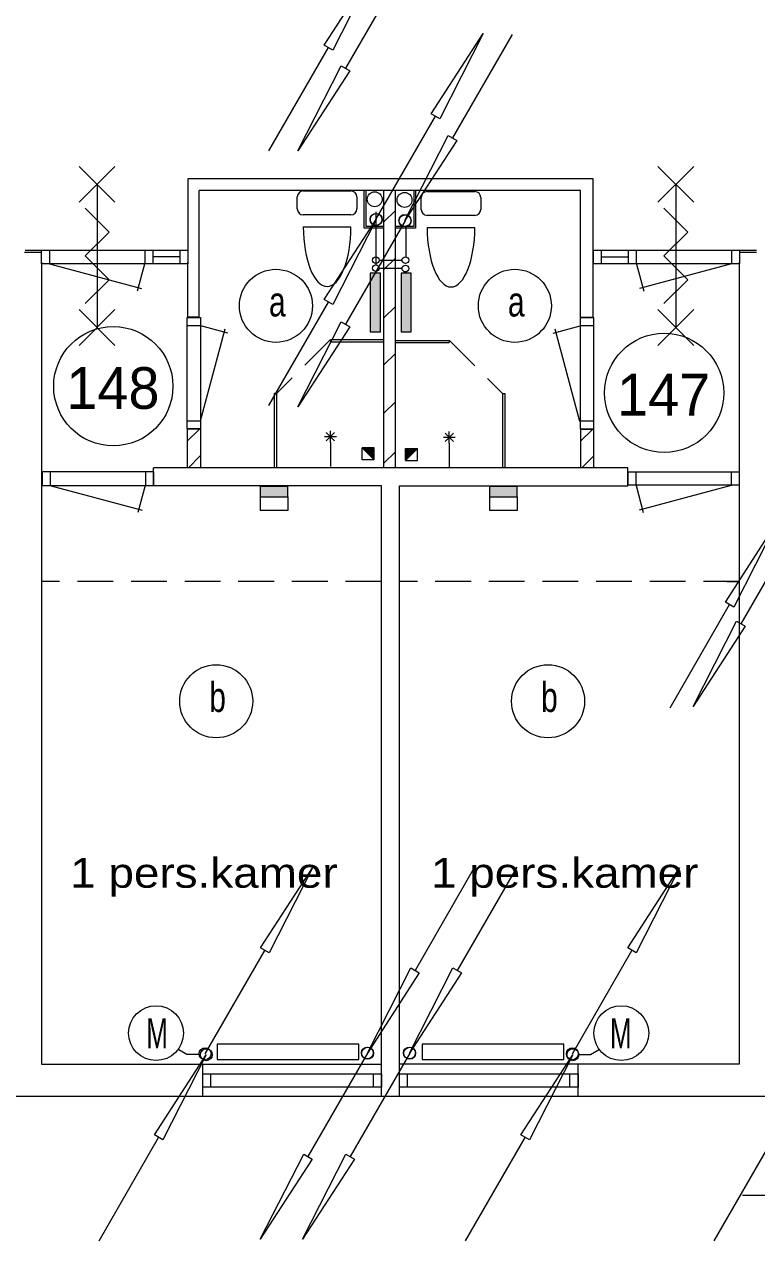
# Model space of a CAD drawing. Extents: x 295824 to 414724, y 24924 to 109024.
# Drawn here: x 319942 to 326087, y 61088 to 71286 of the extents above; entities that cross this region are included whole.
import ezdxf
from ezdxf.enums import TextEntityAlignment as Align

# ---------------------------------------------------------------- set-up
doc = ezdxf.new("R2010")
doc.units = 0
doc.header["$LTSCALE"] = 100
doc.linetypes.add('LONG_DASHED', pattern=[7.5, 6, -1.5])
doc.linetypes.add('MEDIUM_DASHED', pattern=[4.5, 3, -1.5])
doc.layers.add('16', color=7, linetype='Continuous', lineweight=13)
doc.layers.add('61', color=7, linetype='Continuous', lineweight=13)

msp = doc.modelspace()

# ---------------------------------------------------------------- hatches: boundary and pattern name
at = {"layer": '16'}
for points in [[(322843.9, 68706.6), (322929.4, 68706.6), (322929.4, 69198.8), (322843.9, 69198.8)], [(323103.1, 68706.6), (323188.5, 68706.6), (323188.5, 69198.8), (323103.1, 69198.8)], [(322152.7, 67410.5), (321921.2, 67410.5), (321921.2, 67324), (322152.7, 67324)], [(324077.6, 67410.5), (323846.1, 67410.5), (323846.1, 67324), (324077.6, 67324)]]:
    msp.add_hatch(color=256, dxfattribs=at).paths.add_polyline_path(points)
at = {"layer": '61'}
for points in [[(322777.9, 67734.4), (322877.9, 67634.4), (322877.9, 67734.4)], [(323240.3, 67729), (323140.3, 67629), (323140.3, 67729)]]:
    msp.add_hatch(color=256, dxfattribs=at).paths.add_polyline_path(points)

# ---------------------------------------------------------------- linework, layer by layer
at = {"layer": '16'}
for p, q in [((323137.1, 71783), (322637.1, 70917)), ((324035.7, 71199.8), (323535.7, 70333.8)), ((321994.5, 70225), (322494.5, 71091)), ((322892.7, 69649.3), (323392.7, 70515.3)), ((322891.2, 69712.6), (322891.2, 69273)), ((323137.1, 69637.5), (322637.1, 68771.5)), ((323111.5, 69237.6), (322919.8, 69237.6)), ((321994.5, 68091.3), (322494.5, 68957.3)), ((321921.2, 67324), (321921.2, 67210.1)), ((323846.1, 67324), (323846.1, 67210.1)), ((326453.4, 67125.5), (325953.4, 66259.5)), ((325360, 65554.4), (325860, 66420.4)), ((323720.3, 64220.2), (323220.3, 63354.2)), ((324073.8, 64220.2), (323573.8, 63354.2)), ((321459.6, 62655.3), (321959.6, 63521.3)), ((324540.4, 62655.3), (325040.4, 63521.3)), ((322822.3, 62658.9), (322322.3, 61792.9)), ((323175.7, 62658.9), (322675.7, 61792.9)), ((320569.4, 61087.9), (321069.4, 61953.9)), ((323644.3, 61087.9), (324144.3, 61953.9)), ((325729.6, 61087.9), (326229.6, 61953.9)), ((325968.1, 61468.4), (327367.3, 61468.4))]:
    msp.add_line(p, q, dxfattribs=at)
at = {"layer": '16', "linetype": 'LONG_DASHED'}
for p, q in [((323142.4, 69589.1), (323142.4, 69334.1)), ((322919.9, 69308.4), (323111.4, 69308.4))]:
    msp.add_line(p, q, dxfattribs=at)
at = {"layer": '16'}
for points in [[(322894.5, 71784), (322530.5, 71070), (322458.5, 71112)], [(323792.7, 71208.3), (323428.7, 70494.3), (323356.7, 70536.3)], [(322237.1, 70224), (322601.1, 70938), (322673.1, 70896)], [(323135.7, 69640.8), (323499.7, 70354.8), (323571.7, 70312.8)], [(322894.5, 69650.3), (322530.5, 68936.3), (322458.5, 68978.3)], [(322843.9, 68706.6), (322929.4, 68706.6), (322929.4, 69198.8), (322843.9, 69198.8)], [(323103.1, 68706.6), (323188.5, 68706.6), (323188.5, 69198.8), (323103.1, 69198.8)], [(322237.1, 68078.5), (322601.1, 68792.5), (322673.1, 68750.5)], [(322152.7, 67410.5), (321921.2, 67410.5), (321921.2, 67324), (322152.7, 67324)], [(324077.6, 67410.5), (323846.1, 67410.5), (323846.1, 67324), (324077.6, 67324)], [(326260, 67113.4), (325896, 66399.4), (325824, 66441.4)], [(325553.4, 65566.5), (325917.4, 66280.5), (325989.4, 66238.5)], [(322359.6, 64214.3), (321995.6, 63500.3), (321923.6, 63542.3)], [(325440.4, 64214.3), (325076.4, 63500.3), (325004.4, 63542.3)], [(322820.3, 62661.2), (323184.3, 63375.2), (323256.3, 63333.2)], [(323173.8, 62661.2), (323537.8, 63375.2), (323609.8, 63333.2)], [(321560.1, 62606.4), (322750, 62606.4), (322750, 62736), (321560.1, 62736)], [(323280.2, 62606.4), (324470.1, 62606.4), (324470.1, 62736), (323280.2, 62736)], [(321469.4, 62646.9), (321105.4, 61932.9), (321033.4, 61974.9)], [(324544.3, 62646.9), (324180.3, 61932.9), (324108.3, 61974.9)], [(321922.3, 61099.9), (322286.3, 61813.9), (322358.3, 61771.9)], [(322275.7, 61099.9), (322639.7, 61813.9), (322711.7, 61771.9)]]:
    msp.add_lwpolyline(points, close=True, dxfattribs=at)
for points in [[(322152.7, 67324), (322152.7, 67210.1), (321921.2, 67210.1)], [(324077.6, 67324), (324077.6, 67210.1), (323846.1, 67210.1)], [(321408.1, 62650.1), (321305.6, 62650.1), (321239.1, 62688.4)], [(324590.2, 62650.1), (324692.7, 62650.1), (324759.2, 62688.4)]]:
    msp.add_lwpolyline(points, dxfattribs=at)
for centre, radius in [((322892.7, 69649), 50), ((322894.5, 69650), 50), ((323135.7, 69641.1), 50), ((323137.1, 69637.8), 50), ((322892, 69308.4), 27.9), ((322892, 69240.6), 27.9), ((323139.4, 69308.4), 27.9), ((323139.4, 69237.6), 27.9), ((321047.6, 62828.1), 229.9), ((324950.7, 62828.1), 229.9), ((321459.6, 62655), 50), ((321469.4, 62646.6), 50), ((322820.3, 62661.5), 50), ((322822.3, 62659.2), 50), ((323173.8, 62661.5), 50), ((323175.7, 62659.2), 50), ((324540.4, 62655), 50), ((324544.3, 62646.6), 50)]:
    msp.add_circle(centre, radius, dxfattribs=at)
at = {"layer": '61'}
for p, q in [((320403, 69794.2), (320703, 70094.2)), ((320703, 69794.2), (320403, 70094.2)), ((325258.8, 69794.2), (325558.8, 70094.2)), ((325558.8, 69794.2), (325258.8, 70094.2)), ((320553, 69944.2), (320553, 68744.2)), ((321409.7, 68829.5), (321409.7, 69891.5)), ((322282.9, 69888.5), (322682.9, 69888.5)), ((322809.7, 69591.5), (322809.7, 69891.5)), ((322959.7, 67566.5), (322959.7, 69891.5)), ((323056, 67566.5), (323056, 69891.5)), ((323209.7, 69891), (323209.7, 69591)), ((323224.7, 69891), (323224.7, 69576)), ((323322.2, 69883.6), (323722.2, 69883.6)), ((325408.8, 69944.2), (325408.8, 68744.2)), ((322232.9, 69738.5), (322232.9, 69838.5)), ((322732.9, 69838.5), (322732.9, 69738.5)), ((323272.2, 69733.6), (323272.2, 69833.6)), ((323772.2, 69833.6), (323772.2, 69733.6)), ((322682.9, 69688.5), (322282.9, 69688.5)), ((323055.4, 69725.6), (322959.6, 69629.8)), ((323722.2, 69683.6), (323322.2, 69683.6)), ((322282.9, 69588.5), (322682.9, 69588.5)), ((322959.7, 69591.5), (322809.7, 69591.5)), ((323209.7, 69591), (323059.7, 69591)), ((323224.7, 69576), (323059.7, 69576)), ((323322.2, 69583.6), (323722.2, 69583.6)), ((319944.4, 69376.4), (320085.5, 69376.4)), ((319949.3, 69391.4), (320090.5, 69391.4)), ((320153.5, 69391.4), (320153.5, 69277.4)), ((320953.5, 69391.4), (320953.5, 69277.4)), ((321020.5, 69391.4), (321020.5, 69277.4)), ((321246.5, 69391.4), (321246.5, 69277.4)), ((324714.9, 68828), (324714.9, 69393.9)), ((324783.1, 69391.4), (324783.1, 69277.4)), ((325009.1, 69391.4), (325009.1, 69277.4)), ((325076.1, 69391.4), (325076.1, 69277.4)), ((325876.1, 69391.4), (325876.1, 69277.4)), ((325944.5, 69376.4), (326085.7, 69376.4)), ((325945.2, 69391.4), (326086.3, 69391.4)), ((320087, 69291.5), (320087, 62566.5)), ((320152.7, 69276.8), (320925.4, 69069.7)), ((320951.1, 69276.2), (320890.3, 69049.3)), ((321246.5, 69337.3), (321020.5, 69337.3)), ((321314.9, 68829.5), (321314.9, 69291.5)), ((323055.4, 69324.7), (322959.6, 69228.9)), ((324783.1, 69337.4), (325009.1, 69337.4)), ((325078.4, 69276.2), (325139.2, 69049.3)), ((325876.9, 69276.8), (325104.1, 69069.8)), ((325940.1, 69291.5), (325940.1, 62566.5)), ((320403, 68594.2), (320703, 68894.2)), ((320703, 68594.2), (320403, 68894.2)), ((323055.4, 68921.3), (322959.6, 68825.5)), ((325258.8, 68594.2), (325558.8, 68894.2)), ((325558.8, 68594.2), (325258.8, 68894.2)), ((321307.4, 67894.7), (321307.4, 68828.7)), ((321307.4, 68761.7), (321421.4, 68761.7)), ((321409.7, 68829.5), (321314.9, 68829.5)), ((321419.5, 67960.9), (321626.5, 68733.6)), ((321420.1, 68759.3), (321646.9, 68698.5)), ((324603, 68755.1), (324376.2, 68694.3)), ((324720.9, 68757.4), (324606.9, 68757.4)), ((324714.9, 68828), (324609.7, 68828)), ((324720.9, 67892), (324720.9, 68824.4)), ((322960.8, 68640.1), (322511.3, 68640.1)), ((322511.3, 68640.1), (322511.3, 68622.1)), ((323057.5, 68634.8), (323506.9, 68634.8)), ((323506.9, 68634.8), (323506.9, 68616.8)), ((324603.7, 67956.6), (324396.6, 68729.4)), ((322960.4, 68622.1), (322511.3, 68622.1)), ((323057.8, 68616.8), (323506.9, 68616.8)), ((323055.4, 68525.3), (322959.6, 68429.5)), ((322060.4, 67572.1), (322060.4, 68192.6)), ((323957.8, 67566.7), (323957.8, 68187.2)), ((323055.4, 68120.7), (322959.6, 68024.9)), ((321307.4, 67961.7), (321421.4, 67961.7)), ((324720.9, 67957.4), (324606.9, 67957.4)), ((321420.8, 67894.7), (321306.8, 67894.7)), ((321420.1, 67891.1), (321310.1, 67891.1)), ((321310.1, 67891.1), (321310.1, 67567.1)), ((321409.8, 67889.9), (321310.1, 67790.2)), ((321420.1, 67891.1), (321420.1, 67567.1)), ((322560.3, 67828.6), (322460.3, 67828.6)), ((322545.6, 67793.2), (322474.9, 67863.9)), ((322545.6, 67863.9), (322474.9, 67793.2)), ((322510.3, 67778.6), (322510.3, 67878.6)), ((323458, 67823.2), (323558, 67823.2)), ((323472.6, 67787.9), (323543.3, 67858.6)), ((323472.6, 67858.6), (323543.3, 67787.9)), ((323508, 67773.2), (323508, 67873.2)), ((324708.2, 67889.9), (324608.5, 67790.2)), ((324719.1, 67891.1), (324609.1, 67891.1)), ((324609.1, 67891.1), (324609.1, 67567.1)), ((324719.1, 67891.1), (324719.1, 67567.1)), ((322510.3, 67778.6), (322510.3, 67578.6)), ((323508, 67773.2), (323508, 67573.2)), ((321418.4, 67667.3), (321318.7, 67567.6)), ((323055.4, 67702.6), (322959.6, 67606.8)), ((324720.5, 67667.3), (324620.8, 67567.6)), ((320158, 67534), (320158, 67420)), ((320958, 67534), (320958, 67420)), ((321025, 67534), (321025, 67420)), ((321420.1, 67567.1), (321310.1, 67567.1)), ((324719.1, 67567.1), (324609.1, 67567.1)), ((325005.7, 67535.1), (325005.7, 67421.1)), ((325072.7, 67535.1), (325072.7, 67421.1)), ((325872.7, 67535.1), (325872.7, 67421.1)), ((320157.3, 67419.4), (320930, 67212.3)), ((320955.7, 67418.7), (320894.9, 67191.9)), ((322940.1, 62296.5), (322940.1, 67416.5)), ((323090.1, 62296.5), (323090.1, 67416.5)), ((325075, 67419.8), (325135.8, 67193)), ((325873.5, 67420.4), (325100.7, 67213.4)), ((320087, 62566.5), (322940.1, 62566.5)), ((321440.7, 62295.3), (321440.7, 62565.3)), ((325940.1, 62566.5), (323090.1, 62566.5)), ((324588.7, 62295.3), (324588.7, 62565.5)), ((321507.4, 62373.6), (321507.4, 62487.5)), ((322872.5, 62373), (322872.5, 62487)), ((323156, 62373.9), (323156, 62487.9)), ((324520.3, 62373.6), (324520.3, 62487.3)), ((326233, 62296.5), (307806, 62296.5))]:
    msp.add_line(p, q, dxfattribs=at)
at = {"layer": '61', "linetype": 'MEDIUM_DASHED'}
for p, q in [((322509.2, 68639.6), (322062.4, 68192.8)), ((323509, 68634.3), (323955.9, 68187.4)), ((322937.9, 66613.1), (320090.8, 66613.1)), ((325940.2, 66613.1), (323091.2, 66613.1)), ((325835.9, 66613.1), (325939.1, 66613.1))]:
    msp.add_line(p, q, dxfattribs=at)
at = {"layer": '61'}
for points in [[(324714.9, 69391.5), (324714.9, 69991.5), (321314.9, 69991.5), (321314.9, 69391.5)], [(324609.7, 68828), (324609.7, 69891.5), (321409.7, 69891.5)], [(322959.7, 69576.5), (322794.7, 69576.5), (322794.7, 69891.5)], [(320453, 69744.2), (320653, 69544.2), (320453, 69344.2), (320653, 69144.2), (320453, 68944.2)], [(325308.8, 69744.2), (325508.8, 69544.2), (325308.8, 69344.2), (325508.8, 69144.2), (325308.8, 68944.2)], [(322042.4, 67572.1), (322042.4, 68192.6), (322060.4, 68192.6)], [(323975.8, 67566.7), (323975.8, 68187.2), (323957.8, 68187.2)], [(322877.9, 67634.4), (322877.9, 67734.4), (322777.9, 67734.4)], [(323140.3, 67629), (323140.3, 67729), (323240.3, 67729)], [(320091, 67534), (320091, 67420), (321025, 67420)], [(321025, 67534), (320091, 67534), (320091, 67420)], [(323089.9, 67416.5), (325004.9, 67416.5), (325004.9, 67566.5), (321025.5, 67566.5)], [(322939.9, 67416.5), (321025.5, 67416.5), (321025.5, 67566.5)], [(325939.7, 67535.1), (325939.7, 67421.1), (325005.7, 67421.1)], [(325005.7, 67535.1), (325939.7, 67535.1), (325939.7, 67421.1)]]:
    msp.add_lwpolyline(points, dxfattribs=at)
for points in [[(321313.5, 69391.4), (321313.5, 69277.4), (320086.5, 69277.4), (320086.5, 69391.4)], [(321313.5, 69391.4), (321313.5, 69277.4), (320086.5, 69277.4), (320086.5, 69391.4)], [(325943.1, 69391.4), (325943.1, 69277.4), (324716.7, 69277.4), (324716.7, 69391.4)], [(325943.1, 69391.4), (325943.1, 69277.4), (324716.7, 69277.4), (324716.7, 69391.4)], [(321307.4, 67894.7), (321307.4, 68828.7), (321421.4, 68828.7), (321421.4, 67894.7)], [(324720.9, 68825.4), (324606.9, 68825.4), (324606.9, 67891.4), (324720.9, 67891.4)], [(322877.9, 67634.4), (322777.9, 67634.4), (322777.9, 67734.4)], [(322777.9, 67734.4), (322877.9, 67634.4), (322877.9, 67734.4)], [(323140.3, 67629), (323240.3, 67629), (323240.3, 67729)], [(323240.3, 67729), (323140.3, 67629), (323140.3, 67729)], [(321440.6, 62373.5), (321440.6, 62487.5), (322939.3, 62487.5), (322939.3, 62373.5)], [(323089.6, 62373.6), (323089.6, 62487.6), (324589, 62487.6), (324589, 62373.6)]]:
    msp.add_lwpolyline(points, close=True, dxfattribs=at)
for centre, radius in [((322882.2, 69819.1), 62.5), ((323132.2, 69813.5), 62.5), ((322053.3, 68925.6), 306.3), ((324057.9, 68925.6), 306.3), ((320688.9, 68251.4), 500), ((325310.5, 68195.7), 500), ((321552.2, 65610.1), 306.3), ((324336.3, 65610.1), 306.3)]:
    msp.add_circle(centre, radius, dxfattribs=at)
for centre, start, end in [((322282.9, 69838.5), 90, 180), ((322682.9, 69838.5), 0, 90), ((323322.2, 69833.6), 90, 180), ((323722.2, 69833.6), 0, 90), ((322282.9, 69738.5), 180, 270), ((322682.9, 69738.5), 270, 0), ((323322.2, 69733.6), 180, 270), ((323722.2, 69733.6), 270, 0)]:
    msp.add_arc(centre, 50, start, end, dxfattribs=at)
for centre in [(322482.9, 69588.5), (323522.2, 69583.6)]:
    msp.add_ellipse(centre, major_axis=(0, -500), ratio=0.4, start_param=4.712389, end_param=7.8539816, dxfattribs=at)

# ---------------------------------------------------------------- texts
at = {"layer": '16', "width": 0.65}
for p in [(320965.3, 62701.4), (324855.8, 62701.4)]:
    msp.add_text('M', height=250, dxfattribs=at).set_placement(p)
at = {"layer": '61'}
for s, width, p in [('a', 0.75, (321995.3, 68836.4)), ('a', 0.75, (323999.9, 68836.4)), ('b', 0.75, (321494.2, 65520.9)), ('b', 0.75, (324278.3, 65520.9)), ('1 pers.kamer', 1.15, (320327.6, 64046.9)), ('1 pers.kamer', 1.15, (323354.8, 64046.9))]:
    msp.add_text(s, height=250, dxfattribs=dict(at, width=width)).set_placement(p)
for s, p in [('148', (320686, 68061.6)), ('147', (325306.2, 68005.8))]:
    msp.add_text(s, height=350, dxfattribs=at).set_placement(p, align=Align.CENTER)

doc.saveas('drawing.dxf')
